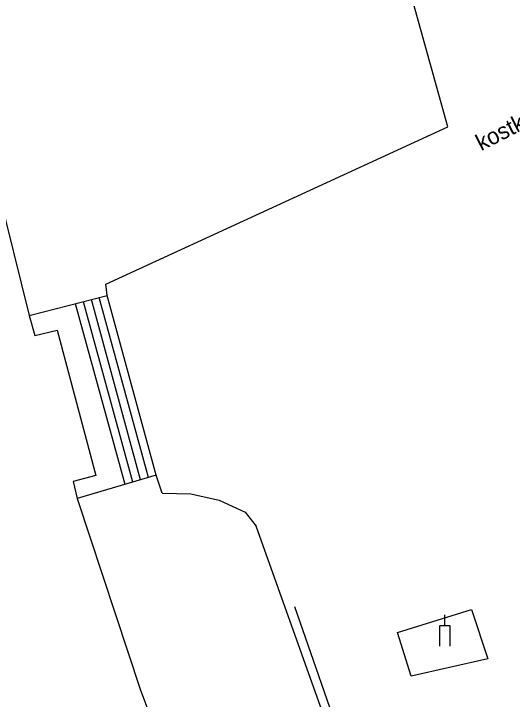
# Model space of a CAD drawing. Extents: x -599098 to -598820, y -1159597 to -1158744.
# Drawn here: x -598959.72 to -598935.31, y -1159287.35 to -1159253.78 of the extents above; entities that cross this region are included whole.
import ezdxf

# ---------------------------------------------------------------- set-up
doc = ezdxf.new("R2010")
doc.units = 0
for name, color, linetype in [('budovy', 7, 'Continuous'), ('kresba', 7, 'Continuous'), ('popisy', 7, 'Continuous'), ('značky IS', 7, 'Continuous')]:
    doc.layers.add(name, color=color, linetype=linetype)

msp = doc.modelspace()

# ---------------------------------------------------------------- linework, layer by layer
at = {"layer": 'budovy'}
for p, q in [((-598961.15, -1159259.76), (-598958.96, -1159268.56)), ((-598958.96, -1159268.56), (-598958.68, -1159269.53)), ((-598958.68, -1159269.53), (-598957.6, -1159269.28)), ((-598957.6, -1159269.28), (-598955.7, -1159276.39)), ((-598955.7, -1159276.39), (-598956.81, -1159276.69)), ((-598956.81, -1159276.69), (-598956.62, -1159277.52)), ((-598956.62, -1159277.52), (-598953.51, -1159286.9)), ((-598953.51, -1159286.9), (-598950.24, -1159295.6))]:
    msp.add_line(p, q, dxfattribs=at)
at = {"layer": 'kresba'}
for p, q in [((-598938.47, -1159259.32), (-598942.8, -1159243.67)), ((-598955.21, -1159267.02), (-598938.47, -1159259.32)), ((-598955.14, -1159267.58), (-598955.21, -1159267.02)), ((-598958.96, -1159268.56), (-598955.14, -1159267.58)), ((-598952.74, -1159276.38), (-598955.14, -1159267.58)), ((-598954.27, -1159276.83), (-598956.7, -1159267.98)), ((-598953.89, -1159276.72), (-598956.3, -1159267.88)), ((-598953.51, -1159276.61), (-598955.91, -1159267.78)), ((-598953.12, -1159276.49), (-598955.53, -1159267.68)), ((-598952.74, -1159276.38), (-598956.62, -1159277.52)), ((-598952.45, -1159277.26), (-598952.74, -1159276.38)), ((-598943.81, -1159290.18), (-598947.84, -1159278.87)), ((-598940.93, -1159284.08), (-598937.31, -1159282.95)), ((-598937.31, -1159282.95), (-598936.51, -1159285.36)), ((-598940.26, -1159286.22), (-598940.93, -1159284.08)), ((-598936.51, -1159285.36), (-598940.26, -1159286.22))]:
    msp.add_line(p, q, dxfattribs=at)
for points in [[(-598952.45, -1159277.26), (-598951.04, -1159277.28), (-598949.66, -1159277.6), (-598948.39, -1159278.19), (-598947.84, -1159278.87)], [(-598925.282, -1159290.426), (-598929.51, -1159290.49), (-598941.79, -1159290.95), (-598942.48, -1159290.86), (-598943.05, -1159290.51), (-598943.45, -1159290), (-598945.95, -1159282.82)]]:
    msp.add_lwpolyline(points, dxfattribs=at)
at = {"layer": 'značky IS'}
msp.add_line((-598938.61, -1159283.74), (-598938.61, -1159283.21), dxfattribs=at)
msp.add_lwpolyline([(-598938.86, -1159284.74), (-598938.86, -1159283.74), (-598938.36, -1159283.74), (-598938.36, -1159284.74)], dxfattribs=at)

# ---------------------------------------------------------------- texts
at = {"layer": 'popisy'}
msp.add_text('kostky', height=0.8, rotation=27.0511, dxfattribs=at).set_placement((-598936.833, -1159260.512))

doc.saveas('drawing.dxf')
